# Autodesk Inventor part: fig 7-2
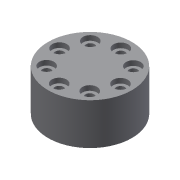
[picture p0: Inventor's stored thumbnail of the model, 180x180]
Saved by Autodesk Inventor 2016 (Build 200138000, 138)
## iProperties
Created: 2004-05
Part Number: fig 7-2
Document SubType Name: Modeling
Designer: CADCIM Technologies
Manufacturer: Standard
Standards Organization: Custom
Density: 1 g/cm^3
Material: Generic
Appearance: Default
Author: CADCIM Technologies
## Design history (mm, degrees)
sketch "Sketch1"
  geometry: C1 r 17.175 at (0, 0)
  constraints: 1 centre point
extrude "Extrusion1" new body sketch "Sketch1" distance "d0" = 17; taper "d1" = 0 deg
sketch "Sketch2"
  geometry: 1 further point
hole "Hole1" sketch "Sketch2" at (12.571, -0.074) diameter "d2" = 3.5; stored, may be unused: countersink angle "d6" = 90 deg, drill point angle "d8" = 118 deg; dims "d3" = 6, "d4" = 6, "d5" = 2, "d7" = 8
pattern_circular "Circular Pattern1" dims angle "d11" = 360 deg
body "Solid1"
